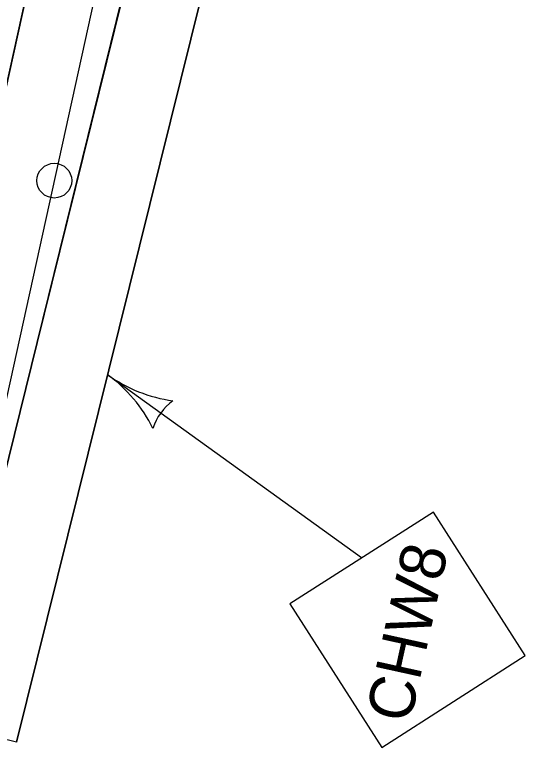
# Model space of a CAD drawing. Extents: x 14104283 to 14120882, y 8635219 to 8671666.
# Drawn here: x 14107829.4 to 14107910.3, y 8639052.5 to 8639168.6 of the extents above; entities that cross this region are included whole.
import ezdxf

# ---------------------------------------------------------------- set-up
doc = ezdxf.new("R2010")
doc.units = 0
for name, color, linetype in [('Cell', 7, 'Continuous'), ('dsnPaintPlaceChannelizingLaneWhite', 7, 'Continuous'), ('dsnPaintPlaceChannelizingLaneYellow', 7, 'Continuous'), ('dsnPaintRemoveDoubleCenterLineYellow', 7, 'Continuous'), ('dsnShadingPaved', 7, 'Continuous'), ('dsnStdLabel', 7, 'Continuous'), ('dsnStgShadingPrevPav', 7, 'Continuous'), ('Shape', 7, 'Continuous')]:
    doc.layers.add(name, color=color, linetype=linetype)

msp = doc.modelspace()

# ---------------------------------------------------------------- linework, layer by layer
at = {"layer": 'Cell'}
msp.add_circle((14107835.7, 8639142.26), 2.75, dxfattribs=at)
at = {"layer": 'dsnPaintPlaceChannelizingLaneWhite'}
msp.add_line((14107829.72, 8639053.3), (14107877.74, 8639247.29), dxfattribs=at)
at = {"layer": 'dsnPaintPlaceChannelizingLaneYellow'}
msp.add_line((14107865.82, 8639249.91), (14107818.04, 8639056.04), dxfattribs=at)
at = {"layer": 'dsnPaintRemoveDoubleCenterLineYellow'}
msp.add_line((14107818.07, 8639056.18), (14107866.09, 8639250.41), dxfattribs=at)
at = {"layer": 'dsnShadingPaved'}
for p, q in [((14107818.04, 8639056.04), (14107865.82, 8639249.91)), ((14107877.74, 8639247.29), (14107829.72, 8639053.3)), ((14107829.72, 8639053.3), (14107818.04, 8639056.04))]:
    msp.add_line(p, q, dxfattribs=at)
at = {"layer": 'dsnStdLabel'}
msp.add_line((14107884.36, 8639082.47), (14107844.13, 8639111.51), dxfattribs=at)
msp.add_lwpolyline([(14107887.54, 8639052.45), (14107910.28, 8639067), (14107895.73, 8639089.75), (14107872.99, 8639075.2)], close=True, dxfattribs=at)
for centre, radius, start, end in [((14107830.7, 8639092.9), 22.95, 26.1067, 54.178), ((14107857.56, 8639130.12), 22.95, 234.1779, 262.2491), ((14107859.73, 8639100.25), 8.86, 126.4437, 161.9122)]:
    msp.add_arc(centre, radius, start, end, dxfattribs=at)
at = {"layer": 'dsnStgShadingPrevPav'}
msp.add_line((14107806.3, 8639058.6), (14107860.16, 8639302.55), dxfattribs=at)
at = {"layer": 'Shape'}
for p, q in [((14107816.84, 8639056.28), (14107884.58, 8639364.69)), ((14107860.17, 8639302.55), (14107806.31, 8639058.6))]:
    msp.add_line(p, q, dxfattribs=at)

# ---------------------------------------------------------------- texts
at = {"layer": 'dsnStdLabel'}
msp.add_text('CHW8', height=7.2, rotation=77.6078, dxfattribs=at).set_placement((14107892.02, 8639056.08))

doc.saveas('drawing.dxf')
